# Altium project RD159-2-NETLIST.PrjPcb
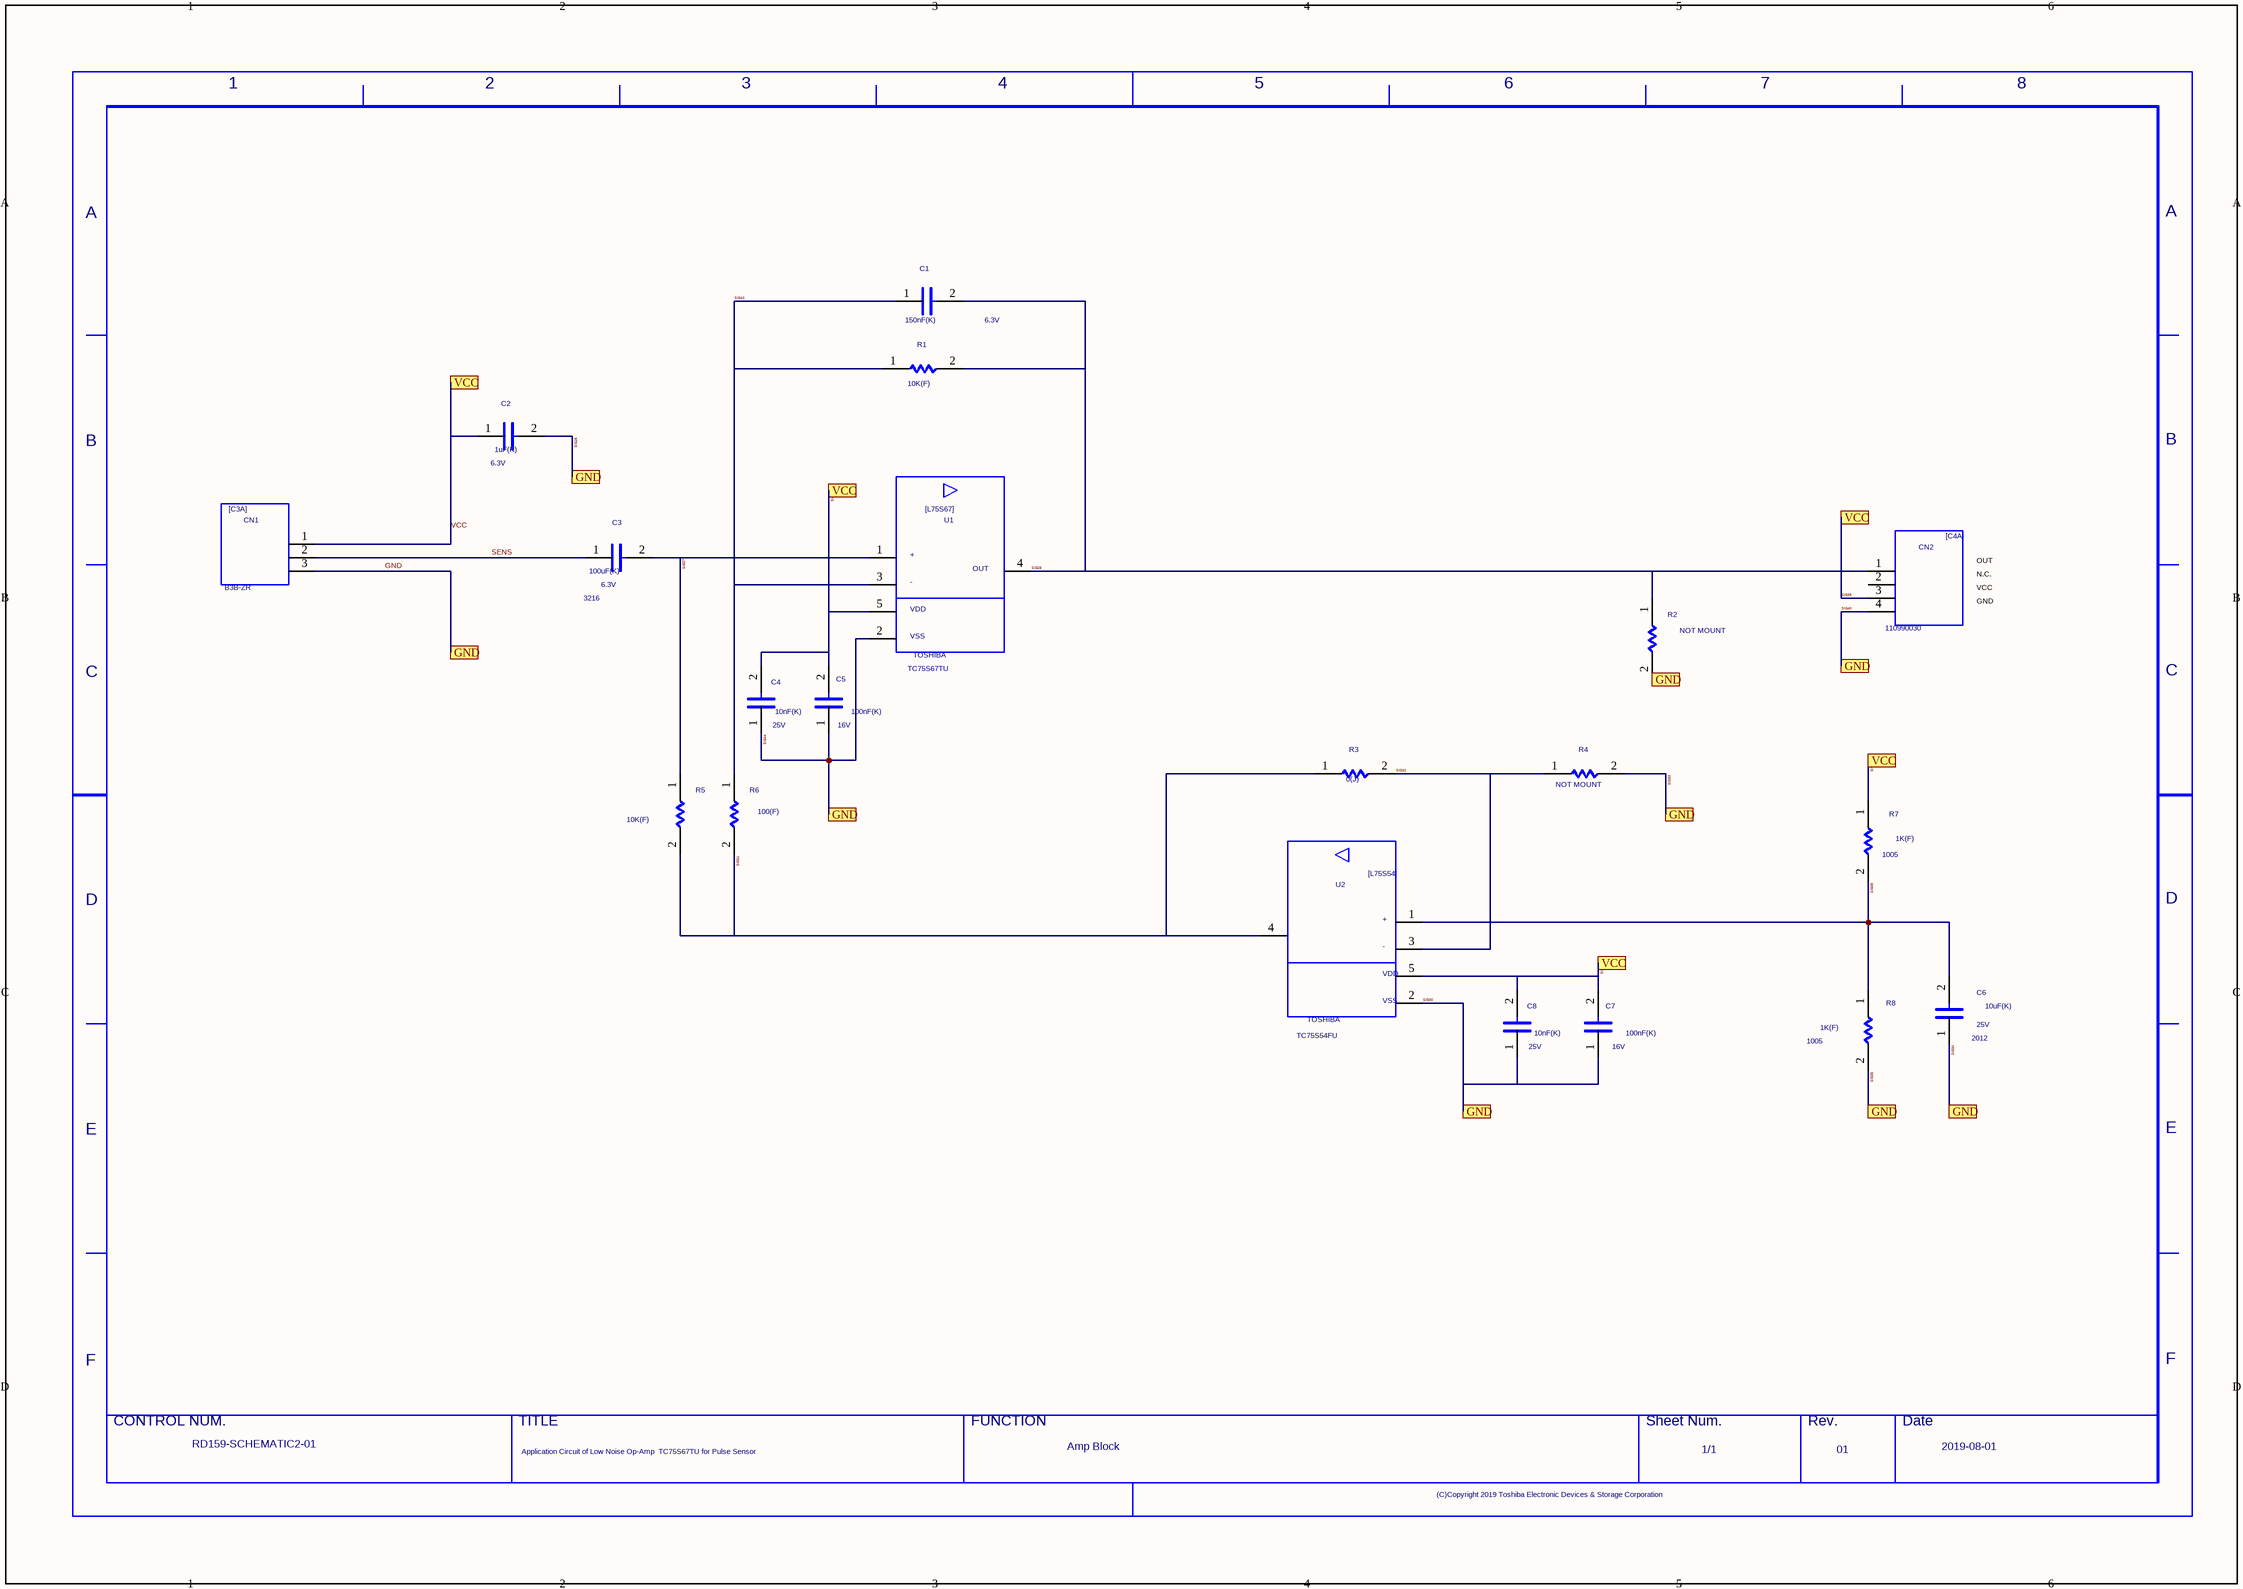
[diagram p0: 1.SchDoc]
1 sheet, 21 parts. Net scope: flat (ports and power ports of the same name join across sheets).

## Sheet 1.SchDoc
size 420 x 297 mm

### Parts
C1  VAL2: 6.3V  VAL1: 150nF(K)  (hidden comment: C)
C2  VAL2: 6.3V  VAL1: 1uF(K)  (hidden comment: C)
C3  SIZECODESMD: 3216  VAL2: 6.3V  VAL1: 100uF(K)  (hidden comment: C)
C4  VAL2: 25V  VAL1: 10nF(K)  (hidden comment: C)
C5  VAL2: 16V  VAL1: 100nF(K)  (hidden comment: C)
C6  SIZECODESMD: 2012  VAL2: 25V  VAL1: 10uF(K)  (hidden comment: C)
C7  VAL2: 16V  VAL1: 100nF(K)  (hidden comment: C)
C8  VAL2: 25V  VAL1: 10nF(K)  (hidden comment: C)
CN1  VAL3: B3B-ZR  (hidden comment: C3A)
CN2  VAL3: 110990030  (hidden comment: C4A)
R1  VAL1: 10K(F)  (hidden comment: R)
R2  NOTMOUNT: NOT MOUNT  (hidden comment: R)
R3  VAL1: 0(J)  (hidden comment: R)
R4  NOTMOUNT: NOT MOUNT  (hidden comment: R)
R5  VAL1: 10K(F)  (hidden comment: R)
R6  VAL1: 100(F)  (hidden comment: R)
R7  SIZECODESMD: 1005  VAL1: 1K(F)  (hidden comment: R)
R8  SIZECODESMD: 1005  VAL1: 1K(F)  (hidden comment: R)
U1  USERCOMPTEXT3: TOSHIBA  VAL3: TC75S67TU  (hidden comment: L75S67)
U2  USERCOMPTEXT3: TOSHIBA  VAL3: TC75S54FU  (hidden comment: L75S54)
U?  DATE: 2019-08-01  REVISION: 01  SHEETNUMBER: 1/1  FUNCTION: Amp Block  TITLE: Application Circuit of Low Noise Op-Amp / TC75S67TU for Pulse Sensor  DRAWINGNUMBER: RD159-SCHEMATIC2-01  (hidden comment: WAKU_DEF100)

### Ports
GND, VCC

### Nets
GND: C2.2 C4.1 C5.1 C6.1 C7.1 C8.1 CN1.3 CN2.4 R2.2 R4.2 R8.2 U1.2 U2.2 ; port GND  [also labelled SIG25, SIG30, SIG33, SIG34, SIG35, SIG40, SIG44]
SENS: C3.1 CN1.2
SIG27: C3.2 R5.1 U1.1
SIG28: C1.2 CN2.1 R1.2 R2.1 U1.4
SIG31: R3.1 R5.2 R6.2 U2.4
SIG32: R3.2 R4.1 U2.3
SIG36: C2.1 C4.2 C5.2 C7.2 C8.2 CN1.1 CN2.3 R7.1 U1.5 U2.5 ; port VCC  [also labelled SIG37, SIG39, SIG41, VCC]
SIG38: C6.2 R7.2 R8.1 U2.1
SIG43: C1.1 R1.1 R6.1 U1.3

Not connected (* = marked no-connect by the designer): CN2 2

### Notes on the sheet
- OUT
- N.C.
- VCC
- GND

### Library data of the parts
C1 = C: PARTNAME: GDM030001370; OriginalSymbolOrigin: (2540,7620); MAXGCOUNT: 1; COMPONENTNAME: GDM030001370_package; SIZECODESMD: 1005
C2 = C: PARTNAME: GDM030000207; OriginalSymbolOrigin: (2540,7620); MAXGCOUNT: 1; COMPONENTNAME: GDM030000207_package; SIZECODESMD: 1005
C3 = C: PARTNAME: GDM030002243; OriginalSymbolOrigin: (2540,7620); COMPONENTNAME: GDM030002243_package; MAXGCOUNT: 1
C4 C8 = C: PARTNAME: GAS030000012; OriginalSymbolOrigin: (2540,7620); MAXGCOUNT: 1; COMPONENTNAME: GAS030000012_package; SIZECODESMD: 1005
C5 C7 = C: PARTNAME: GAS030000176; OriginalSymbolOrigin: (2540,7620); MAXGCOUNT: 1; COMPONENTNAME: GAS030000176_package; SIZECODESMD: 1005
C6 = C: PARTNAME: GDM030002136; OriginalSymbolOrigin: (2540,7620); COMPONENTNAME: GDM030002136_package; MAXGCOUNT: 1
CN1 = C3A: PARTNAME: K22S001Q; OUMEPARTTYPE: CN; SAVEAREA0: -6798,-236,26764,20869; TIME: 09:53:04; UPDATEUSER: tomizawa-y; UPDATETIME: 09:53:12; SAVECOUNT: 2; OriginalSymbolOrigin: (2540,17780); COMPONENTNAME: K22S001Q_package; MAXGCOUNT: 1
CN2 = C4A: PARTNAME: K22S001P; OUMEPARTTYPE: CN; SAVEAREA0: -8845,-265,28754,23475; SAVECOUNT: 22; TIME: 13:28:28; UPDATEUSER: tomizawa-y; UPDATETIME: 15:03:27; OriginalSymbolOrigin: (2540,20320); COMPONENTNAME: K22S001P_package; MAXGCOUNT: 1
R1 = R: PARTNAME: GDM010001330; OriginalSymbolOrigin: (5080,5080); VAL2: 100mW; MAXGCOUNT: 1; COMPONENTNAME: GDM010001330_package; SIZECODESMD: 1005
R2 = R: PARTNAME: GAS010000128; OriginalSymbolOrigin: (5080,5080); MAXGCOUNT: 1; COMPONENTNAME: GAS010000128_package; SIZECODESMD: 1005
R3 = R: PARTNAME: GDM010000374; OriginalSymbolOrigin: (5080,5080); MAXGCOUNT: 1; COMPONENTNAME: GDM010000374_package; SIZECODESMD: 1005; VAL2: 1A
R4 = R: PARTNAME: GDM010000374; OriginalSymbolOrigin: (5080,5080); MAXGCOUNT: 1; COMPONENTNAME: GDM010000374_package; SIZECODESMD: 1005
R5 = R: PARTNAME: GDM010001330; OriginalSymbolOrigin: (5080,5080); MAXGCOUNT: 1; COMPONENTNAME: GDM010001330_package; SIZECODESMD: 1005; VAL2: 100mW
R6 = R: PARTNAME: G36010118534; OriginalSymbolOrigin: (5080,5080); MAXGCOUNT: 1; COMPONENTNAME: G36010118534_package; SIZECODESMD: 1005; VAL2: 100mW
R7 R8 = R: PARTNAME: GDM010003334; OriginalSymbolOrigin: (5080,5080); MAXGCOUNT: 1; COMPONENTNAME: GDM010003334_package; VAL2: 100mW
U1 = L75S67: PARTNAME: K47S002A; OUMEPARTTYPE: IC; TIME: 16:27:13; UPDATEUSER: w90028dm; UPDATETIME: 15:17:13; SAVECOUNT: 13; SAVEAREA0: -43421,-10273,73920,48138; OriginalSymbolOrigin: (5080,35560); COMPONENTNAME: K47S002A_package; MAXGCOUNT: 1
U2 = L75S54: PARTNAME: K4703589; OUMEPARTTYPE: IC; TIME: 16:27:13; UPDATEUSER: 19990028; UPDATETIME: 13:02:06; SAVECOUNT: 8; SAVEAREA0: -72307,-25685,103712,61936; OriginalSymbolOrigin: (5080,35560); COMPONENTNAME: K4703589_package; MAXGCOUNT: 1
U? = WAKU_DEF100: PLOTTIME: HH:MM; SAVEAREA0: 198008,-65938,436964,90161; TIME: 14:30:25; UPDATEUSER: cae; UPDATETIME: 18:10:13; SAVECOUNT: 4; OriginalSymbolOrigin: (10160,284480)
